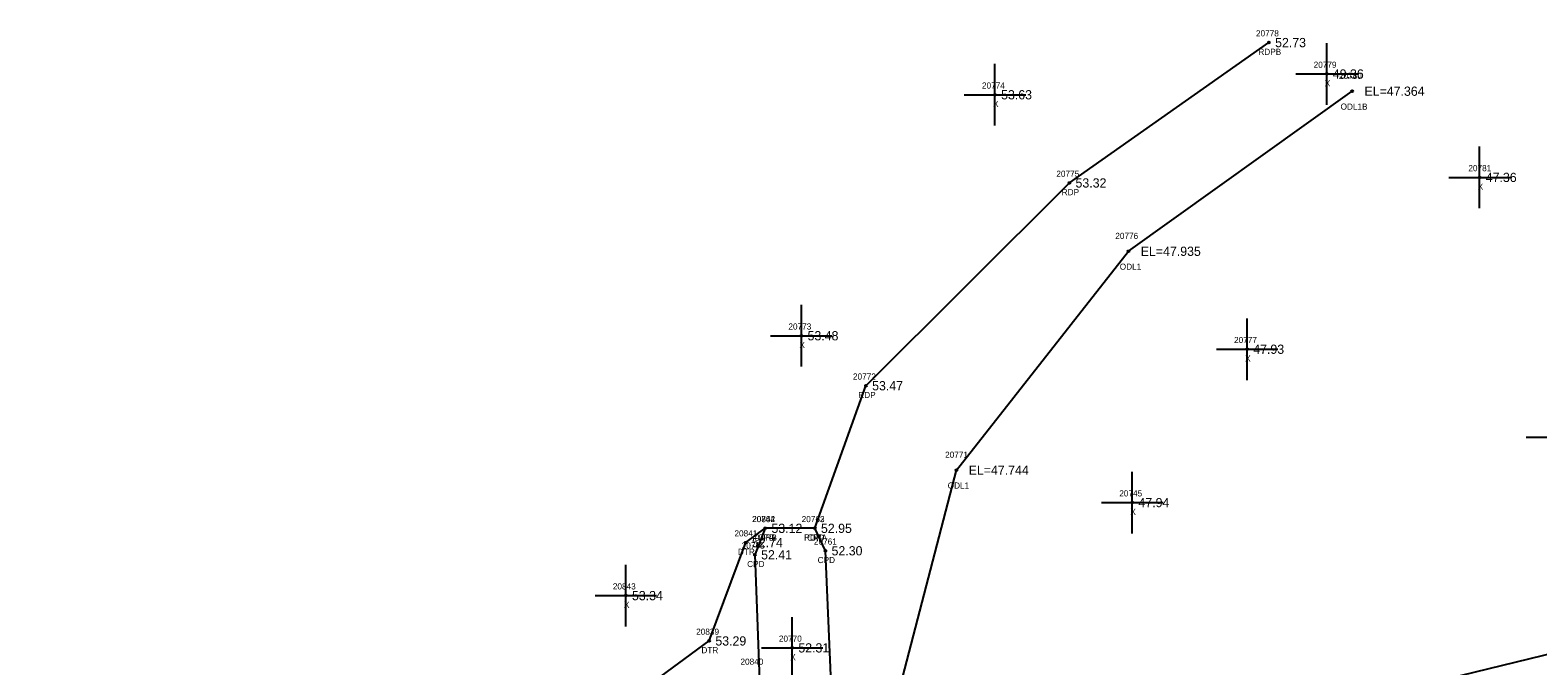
# Model space of a CAD drawing. Extents: x 2420351 to 2422725, y 845330 to 846558.
# Drawn here: x 2421390.4 to 2421635.3, y 846025.1 to 846128.3 of the extents above; entities that cross this region are included whole.
import ezdxf

# ---------------------------------------------------------------- set-up
doc = ezdxf.new("R2010")
doc.units = 0
for name, color, linetype in [('RD_EX_Conc', 7, 'Continuous'), ('RD_EX_Conc_txCode', 7, 'Continuous'), ('RD_EX_DR_ErosCtrl', 7, 'Continuous'), ('RD_EX_DR_ErosCtrl_txCode', 7, 'Continuous'), ('RD_EX_H2O', 7, 'Continuous'), ('RD_EX_H2O_txCode', 7, 'Continuous'), ('RD_EX_Misc', 7, 'Continuous'), ('RD_EX_Misc_txCode', 7, 'Continuous'), ('RD_EX_TX_Conc_ELEV', 7, 'Continuous'), ('RD_EX_TX_DR_ErosCtrl_ELEV', 7, 'Continuous'), ('RD_EX_TX_H2O_ELEV', 7, 'Continuous'), ('RD_EX_TX_Misc_ELEV', 7, 'Continuous'), ('RD_SMD_Locator', 7, 'Continuous')]:
    doc.layers.add(name, color=color, linetype=linetype)

msp = doc.modelspace()

# ---------------------------------------------------------------- linework, layer by layer
at = {"layer": 'RD_EX_Conc'}
msp.add_lwpolyline([(2421518.9, 846011.73), (2421520.79, 846015.94), (2421519.59, 846043.78), (2421517.87, 846047.43), (2421509.82, 846047.43), (2421508.14, 846043.13), (2421509.15, 846015.43), (2421510.99, 846011.42)], dxfattribs=at)
at = {"layer": 'RD_EX_DR_ErosCtrl'}
msp.add_lwpolyline([(2421517.87, 846047.43), (2421526.18, 846070.59), (2421559.23, 846103.53), (2421591.66, 846126.33)], dxfattribs=at)
at = {"layer": 'RD_EX_H2O'}
for points in [[(2421769.97, 845784.59), (2421757.53, 845787.6), (2421742.96, 845811.73), (2421745.62, 845824.92), (2421731.55, 845840.59), (2421714.37, 845860.98), (2421703.55, 845865.16), (2421670.27, 845895.91), (2421653.18, 845938.84), (2421661.84, 845966.62), (2421645.65, 846012.9), (2421638.29, 846027.24), (2421576.72, 846012.28), (2421545.4, 846011.31), (2421531.8, 846021.91), (2421540.87, 846056.88), (2421568.83, 846092.43), (2421605.18, 846118.43)], [(2421712.23, 845851.64), (2421696.17, 845853.46), (2421673.72, 845844.59), (2421672.85, 845833.86), (2421657.19, 845821.05), (2421639.52, 845822.79), (2421628.75, 845828.72), (2421620.88, 845834.5), (2421598.01, 845848.76), (2421559.66, 845849.82), (2421519.66, 845839.33), (2421490.26, 845831.77), (2421489.16, 845834.56), (2421488.34, 845838.76), (2421481.47, 845840.1), (2421478.52, 845840.67), (2421462.88, 845836.78), (2421401.68, 845880.53), (2421390.37, 845914.71), (2421413.41, 845969.29), (2421455.53, 845995.93), (2421500.71, 846029.14), (2421506.65, 846045.11), (2421509.82, 846047.43)]]:
    msp.add_lwpolyline(points, dxfattribs=at)
at = {"layer": 'RD_EX_Misc'}
for p, q in [((2421601.04, 846116.23), (2421601.04, 846126.23)), ((2421547.14, 846112.85), (2421547.14, 846122.85)), ((2421596.04, 846121.23), (2421606.04, 846121.23)), ((2421542.14, 846117.85), (2421552.14, 846117.85)), ((2421625.89, 846099.43), (2421625.89, 846109.43)), ((2421620.89, 846104.43), (2421630.89, 846104.43)), ((2421515.69, 846073.71), (2421515.69, 846083.71)), ((2421588.11, 846071.52), (2421588.11, 846081.52)), ((2421510.69, 846078.71), (2421520.69, 846078.71)), ((2421583.11, 846076.52), (2421593.11, 846076.52)), ((2421633.45, 846062.23), (2421643.45, 846062.23)), ((2421569.46, 846046.61), (2421569.46, 846056.61)), ((2421564.46, 846051.61), (2421574.46, 846051.61)), ((2421487.16, 846031.5), (2421487.16, 846041.5)), ((2421482.16, 846036.5), (2421492.16, 846036.5)), ((2421514.19, 846023.01), (2421514.19, 846033.01)), ((2421509.19, 846028.01), (2421519.19, 846028.01))]:
    msp.add_line(p, q, dxfattribs=at)
at = {"layer": 'RD_SMD_Locator'}
for centre in [(2421591.66, 846126.33), (2421601.04, 846121.23), (2421547.14, 846117.85), (2421605.18, 846118.43), (2421559.23, 846103.53), (2421625.89, 846104.43), (2421568.83, 846092.43), (2421515.69, 846078.71), (2421588.11, 846076.52), (2421526.18, 846070.59), (2421540.87, 846056.88), (2421569.46, 846051.61), (2421509.82, 846047.43), (2421509.82, 846047.43), (2421517.87, 846047.43), (2421517.87, 846047.43), (2421506.65, 846045.11), (2421508.14, 846043.13), (2421519.59, 846043.78), (2421487.16, 846036.5), (2421500.71, 846029.14), (2421514.19, 846028.01)]:
    msp.add_circle(centre, 0.15, dxfattribs=at)

# ---------------------------------------------------------------- texts
at = {"layer": 'RD_EX_Conc_txCode'}
for s, p in [('20764', (2421507.67, 846048.43)), ('20762', (2421515.73, 846048.43)), ('CPD', (2421508.56, 846045.43)), ('CPD', (2421516.62, 846045.43)), ('20765', (2421505.99, 846044.13)), ('20761', (2421517.73, 846044.78)), ('CPD', (2421506.88, 846041.13)), ('CPD', (2421518.33, 846041.78))]:
    msp.add_text(s, height=1, dxfattribs=at).set_placement(p)
at = {"layer": 'RD_EX_DR_ErosCtrl_txCode'}
for s, p in [('20778', (2421589.55, 846127.33)), ('RDPB', (2421589.94, 846124.33)), ('20775', (2421557.11, 846104.53)), ('RDP', (2421557.98, 846101.53)), ('20772', (2421524.07, 846071.59)), ('RDP', (2421524.93, 846068.59)), ('20763', (2421515.73, 846048.43)), ('RDPA', (2421516.13, 846045.43))]:
    msp.add_text(s, height=1, dxfattribs=at).set_placement(p)
at = {"layer": 'RD_EX_H2O_txCode'}
for s, p in [('20780', (2421603.03, 846120.43)), ('ODL1B', (2421603.3, 846115.43)), ('20776', (2421566.69, 846094.43)), ('ODL1', (2421567.42, 846089.43)), ('20771', (2421539.04, 846058.88)), ('ODL1', (2421539.46, 846053.88)), ('20842', (2421507.7, 846048.43)), ('20841', (2421504.81, 846046.11)), ('DTRB', (2421508.08, 846045.43)), ('DTR', (2421505.38, 846043.11)), ('20839', (2421498.59, 846030.14)), ('DTR', (2421499.44, 846027.14)), ('20840', (2421505.79, 846025.27))]:
    msp.add_text(s, height=1, dxfattribs=at).set_placement(p)
at = {"layer": 'RD_EX_Misc_txCode'}
for s, p in [('20779', (2421598.92, 846122.23)), ('X', (2421600.73, 846119.23)), ('20774', (2421545.03, 846118.85)), ('X', (2421546.83, 846115.85)), ('20781', (2421624.06, 846105.43)), ('X', (2421625.58, 846102.43)), ('20773', (2421513.58, 846079.71)), ('20777', (2421585.99, 846077.52)), ('X', (2421515.38, 846076.71)), ('X', (2421587.79, 846074.52)), ('20745', (2421567.34, 846052.61)), ('X', (2421569.14, 846049.61)), ('20843', (2421485.05, 846037.5)), ('X', (2421486.85, 846034.5)), ('20770', (2421512.03, 846029.01)), ('X', (2421513.88, 846026.01))]:
    msp.add_text(s, height=1, dxfattribs=at).set_placement(p)
at = {"layer": 'RD_EX_TX_Conc_ELEV'}
for s, p in [('53.12', (2421510.82, 846046.68)), ('52.95', (2421518.87, 846046.68)), ('52.30', (2421520.59, 846043.03)), ('52.41', (2421509.14, 846042.38))]:
    msp.add_text(s, height=1.5, dxfattribs=at).set_placement(p)
at = {"layer": 'RD_EX_TX_DR_ErosCtrl_ELEV'}
for s, p in [('52.73', (2421592.66, 846125.58)), ('53.32', (2421560.23, 846102.78)), ('53.47', (2421527.18, 846069.84)), ('52.95', (2421518.87, 846046.68))]:
    msp.add_text(s, height=1.5, dxfattribs=at).set_placement(p)
at = {"layer": 'RD_EX_TX_H2O_ELEV'}
for s, p in [('EL=47.364', (2421607.18, 846117.68)), ('EL=47.935', (2421570.83, 846091.68)), ('EL=47.744', (2421542.87, 846056.13)), ('53.12', (2421510.82, 846046.68)), ('52.74', (2421507.65, 846044.36)), ('53.29', (2421501.71, 846028.39))]:
    msp.add_text(s, height=1.5, dxfattribs=at).set_placement(p)
at = {"layer": 'RD_EX_TX_Misc_ELEV'}
for s, p in [('49.36', (2421602.04, 846120.48)), ('53.63', (2421548.14, 846117.1)), ('47.36', (2421626.89, 846103.68)), ('53.48', (2421516.69, 846077.96)), ('47.93', (2421589.11, 846075.77)), ('47.94', (2421570.46, 846050.86)), ('53.34', (2421488.16, 846035.75)), ('52.31', (2421515.19, 846027.26))]:
    msp.add_text(s, height=1.5, dxfattribs=at).set_placement(p)

doc.saveas('drawing.dxf')
